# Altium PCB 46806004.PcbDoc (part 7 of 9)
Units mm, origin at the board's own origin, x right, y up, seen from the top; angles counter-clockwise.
Board outline 130 x 105 mm, 8 copper layers (Top Layer, P1-GND, L1-Signal, L2-Signal, L3-Signal, L4-Signal, P2-GND, Bottom Layer), stack 1.63 mm thick; 796 components, 496 nets, 2808 pads, 1195 vias.
Unrouted connection lines stored in the file: 1.
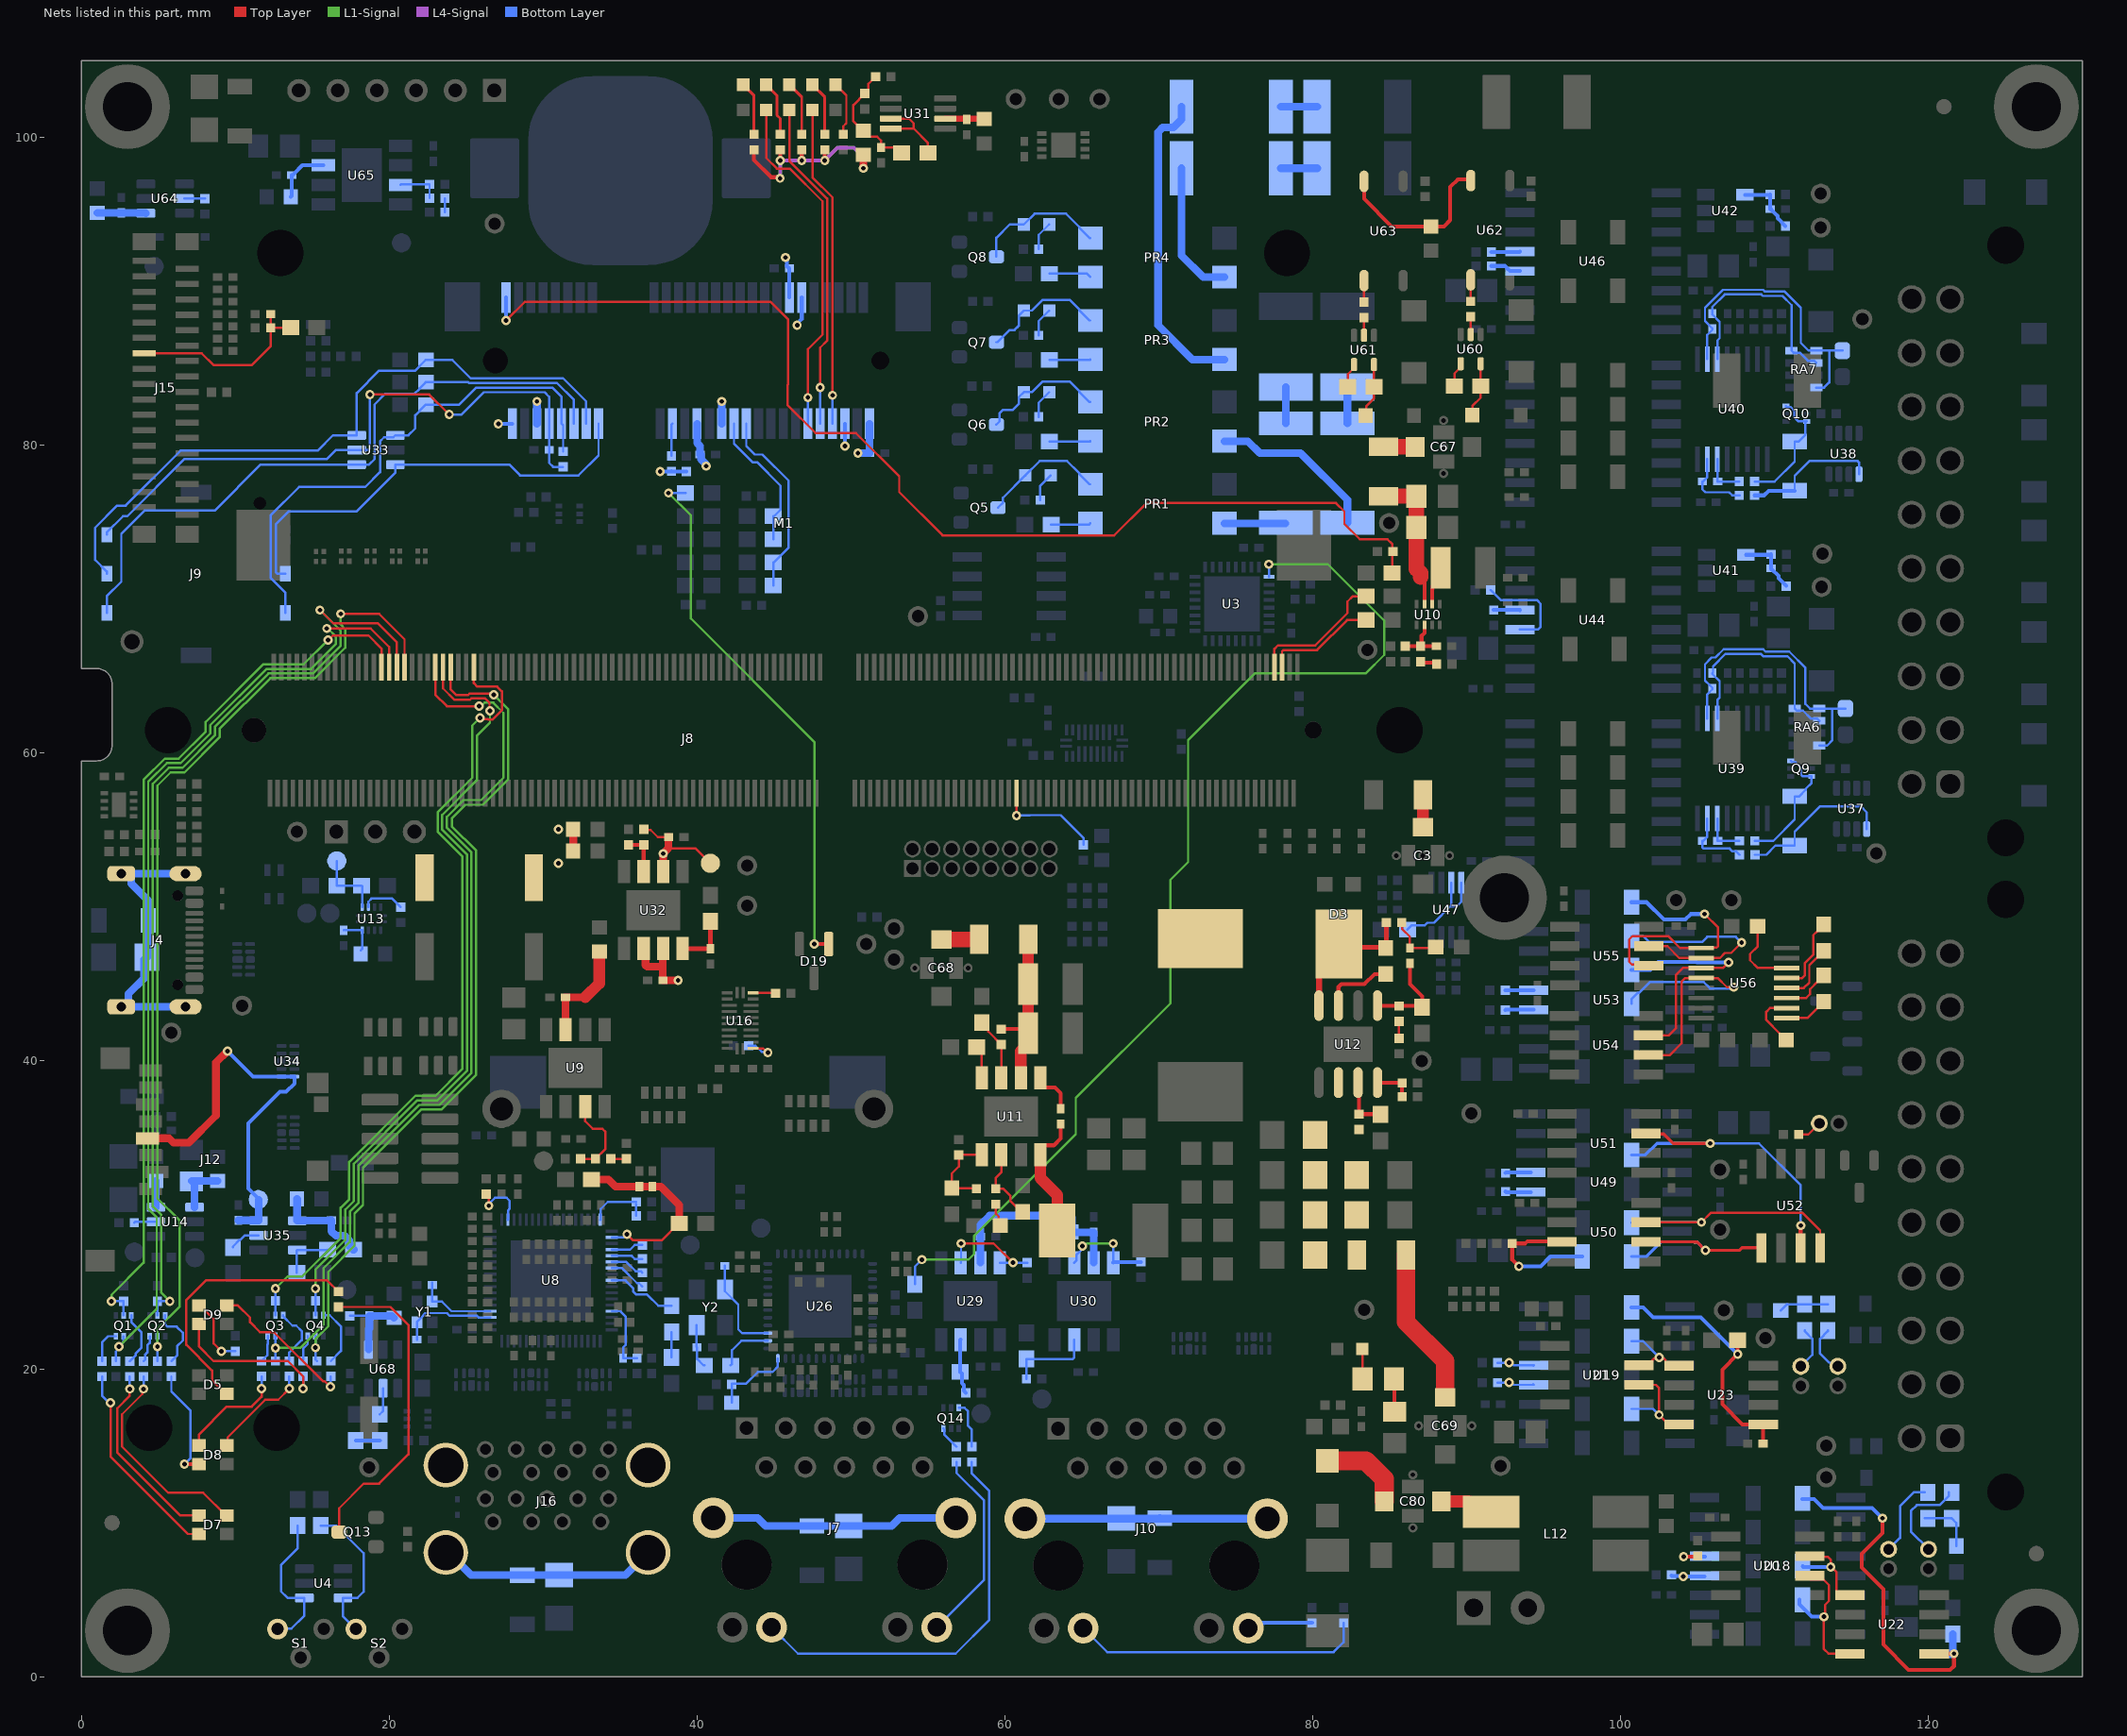
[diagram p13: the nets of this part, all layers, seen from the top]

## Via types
v1: diameter 0.6, hole 0.3, Top Layer to Bottom Layer, tented both sides, 1130 vias
v2: diameter 0.6, hole 0.3, Top Layer to Bottom Layer, 53 vias
v3: diameter 0.3, hole 0.3, Top Layer to Bottom Layer, 12 vias

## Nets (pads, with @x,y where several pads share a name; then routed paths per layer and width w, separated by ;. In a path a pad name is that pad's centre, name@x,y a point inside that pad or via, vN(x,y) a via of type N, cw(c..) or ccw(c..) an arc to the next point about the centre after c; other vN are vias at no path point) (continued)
LEDs.GPIO1: M1.30 Q1.2 R67.2 | length 57.7
  Top Layer w0.15: v1(16.025,67.35) 16.05,67.35 16.35,67.65 18.65,67.65 19.5,66.8 M1.30@19.5,65.6
  L1-Signal w0.15: v1(1.95,24.4) 1.971,24.421 1.971,24.821 4.05,26.9 4.05,58.265 5.435,59.65 6.327,59.65 8.084,61.407 8.084,62.034 11.828,65.778 14.453,65.778 v1(16.025,67.35)
  Bottom Layer w0.15: v1(1.95,24.4) R67.2@2.75,24.4 Q1.2@2.75,23.475
LEDs.GPIO2: M1.32 Q1.5 R70.2 | length 63.1
  Top Layer w0.15: v1(15.95,68.1) 18.8,68.1 20,66.9 M1.32@20,65.6
  L1-Signal w0.15: v1(2.45,21.45) 4.9,23.9 4.9,29.85 4.35,30.4 4.35,58.141 5.559,59.35 6.451,59.35 8.384,61.282 8.384,61.828 12.034,65.478 14.93,65.478 16.55,67.099 16.55,67.567 16.017,68.1 v1(15.95,68.1)
  Bottom Layer w0.15: R70.2@2.25,20.5 2.25,21.128 2.45,21.328 v1(2.45,21.45) 2.456,21.45 2.75,21.744 Q1.5@2.75,22.125
LEDs.GPIO3: M1.34 Q2.2 R71.2 | length 62.4
  Top Layer w0.15: v1(15.5,69.3) 16.35,68.45 19.25,68.45 20.5,67.2 M1.34@20.5,65.6
  L1-Signal w0.15: v1(5.75,24.4) 5.2,24.95 5.2,29.995 4.65,30.545 4.65,58.017 5.683,59.05 6.576,59.05 8.684,61.158 8.684,61.704 12.158,65.178 15.054,65.178 16.85,66.974 16.85,67.95 v1(15.5,69.3)
  Bottom Layer w0.15: Q2.2@4.95,23.475 R71.2@4.95,24.4 v1(5.75,24.4)
LEDs.GPIO4: M1.36 Q2.5 R74.2 | length 64.5
  Top Layer w0.15: v1(16.85,69.05) 19.35,69.05 21,67.4 M1.36@21,65.6
  L1-Signal w0.15: v1(4.95,21.45) 4.95,22.6 6.4,24.05 6.4,29.628 4.95,31.078 4.95,57.892 5.808,58.75 6.7,58.75 8.984,61.034 8.984,61.579 12.283,64.878 15.178,64.878 17.15,66.85 17.15,68.074 16.85,68.374 v1(16.85,69.05)
  Bottom Layer w0.15: R74.2@4.95,20.5 v1(4.95,21.45) Q2.5@4.95,22.125
LEDs.GPIO5: M1.54 Q3.2 R75.2 | length 53
  Top Layer w0.15: M1.54@25.5,65.6 25.5,64.55 25.725,64.325 27.017,64.325 27.325,64.017 27.325,62.783 26.733,62.191 26.429,62.191 26.412,62.208 25.986,62.208 v1(25.9,62.294)
  L1-Signal w0.15: v1(12.614,25.215) 13.399,26 14.35,26 16.85,28.5 16.85,30.475 17.4,31.025 17.4,33.447 21.703,37.75 23.015,37.75 24.75,39.485 24.75,53.3 23.15,54.9 23.15,56.15 25.4,58.4 25.4,61.794 v1(25.9,62.294)
  Bottom Layer w0.15: Q3.2@12.614,23.49 R75.2@12.614,24.415 v1(12.614,25.215)
LEDs.GPIO6: M1.44 Q3.5 R78.2 | length 59.6
  Top Layer w0.15: M1.44@23,65.6 23,63.8 23.75,63.05 v1(25.85,63.05)
  L1-Signal w0.15: v1(12.614,21.365) 14.215,21.365 15.75,22.9 15.75,26.551 17.45,28.251 17.45,30.226 18,30.776 18,33.199 21.951,37.15 23.263,37.15 25.35,39.237 25.35,53.549 23.75,55.149 23.75,55.867 24.839,56.956 25.982,56.956 27.425,58.399 27.425,62.617 26.767,63.275 26.197,63.275 25.972,63.05 v1(25.85,63.05)
  Bottom Layer w0.15: R78.2@12.614,20.515 v1(12.614,21.365) Q3.5@12.614,22.14
LEDs.GPIO7: M1.46 Q4.2 R79.2 | length 51.5
  Top Layer w0.15: M1.46@23.5,65.6 23.5,64.209 24.241,63.468 25.247,63.468 25.354,63.575 26.217,63.575 26.517,63.275 26.517,62.783 v1(26.55,62.75)
  L1-Signal w0.15: v1(15.214,25.215) 15.214,26.44 17.15,28.376 17.15,30.351 17.7,30.901 17.7,33.323 21.827,37.45 23.139,37.45 25.05,39.361 25.05,53.424 23.45,55.024 23.45,55.991 25.7,58.241 25.7,61.137 26.55,61.987 v1(26.55,62.75)
  Bottom Layer w0.15: Q4.2@15.214,23.49 R79.2@15.214,24.415 v1(15.214,25.215)
LEDs.GPIO8: M1.48 Q4.5 R81.2 | length 56.9
  Top Layer w0.15: M1.48@24,65.6 23.995,65.595 23.995,64.588 23.975,64.567 23.975,64.158 24.366,63.768 25.122,63.768 25.23,63.875 26.725,63.875 v1(26.8,63.8)
  L1-Signal w0.15: v1(15.214,21.377) 15.214,21.94 16.05,22.776 16.05,26.3 17.75,28 17.75,30.1 18.3,30.65 18.3,33.074 22.076,36.85 23.388,36.85 25.65,39.112 25.65,53.673 24.075,55.248 24.075,55.767 24.958,56.65 26.1,56.65 27.725,58.275 27.725,62.875 v1(26.8,63.8)
  Bottom Layer w0.15: Q4.5@15.214,22.14 v1(15.214,21.377) 15.214,20.615 R81.2@15.314,20.515
MPCI1_1V5: C180.2 J8.6 J8.28 J8.48 R149.2 U32.6 X55.1 | length 11.7
  Top Layer w0.15: R149.2@36.55,55.05 36.587,55.013 36.987,55.013 37.45,54.55 C180.2@38.15,54.55 ; 38.15,53.825 39.89,53.825 X55.1@40.865,52.85
  Top Layer w0.5: U32.6@37.8,52.3 v1(37.8,53.475) 38.15,53.825 C180.2@38.15,54.55
  Bottom Layer w0.25: v1(49.6,79.95) J8.48@49.6,81.4
  Bottom Layer w0.5: J8.6@29.6,81.4 v1(29.6,82.85) ; J8.28@41.6,81.4 v1(41.6,82.85)
MPCI1_3V3: C168.1 C169.1 C170.2 C171.2 C172.2 C174.2 J8.2 J8.24 J8.39 J8.41 J8.52 L27.2 L28.2 L30.2 R135.2 R141.1 R146.1 R151.2 R152.2 R153.2 U32.2 U32.3 | length 33.3
  Top Layer w0.25: R135.2@43.7,99.2 43.7,98.525 44.808,97.417 45.323,97.417 v1(45.39,97.35) ; v1(45.4,98.5) R151.2@45.4,99.2 ; v1(46.8,98.5) R152.2@46.8,99.2 ; v1(48.3,98.5) R153.2@48.3,99.2
  Top Layer w0.5: L28.2@31.96,53.654 L27.2@31.96,55.054 ; U32.2@36.53,47.3 36.649,47.181 36.649,46.237 36.753,46.133 37.769,46.133 ; C174.2@37.769,45.271 37.769,46.133 ; C174.2@37.79,45.25 v1(38.765,45.25) ; U32.3@37.8,47.3 37.769,47.269 37.769,46.133 ; v1(50.8,98) L30.2@50.8,98.86
  L4-Signal w0.25: v1(45.39,97.35) 45.395,97.355 45.395,98.495 v1(45.4,98.5) v1(46.8,98.5) v1(48.3,98.5) 49.12,99.32 50.18,99.32 50.8,98.7 v1(50.8,98)
  Bottom Layer w0.25: v1(27.09,81.4) J8.2@28,81.4 ; v1(37.6,78.3) 37.608,78.308 38.332,78.308 R141.1@38.34,78.316 ; R141.1@38.356,78.3 R146.1@39.3,78.3 ; v1(45.75,92.2) 45.75,92.105 45.825,92.03 45.825,91.625 45.95,91.5 C172.2@46,91.5 J8.39@46,89.6 ; v1(46.5,87.8) 46.5,87.895 46.8,88.195 J8.41@46.8,89.6
  Bottom Layer w0.5: J8.24@40,81.4 40,80.15 40.2,79.95 C171.2@40.2,79.4 40.25,79.4 40.25,79.095 40.581,78.764 40.581,78.669 v1(40.6,78.65) ; v1(50.45,79.5) C170.2@51.2,79.5 J8.52@51.2,81.4
  other v1: 31,52.85 31,55.05
NetC2_2: C2.2 J10.S R3.1 | length 15.8
  Bottom Layer w0.5: J10.S@61.3,10.269 70.019,10.269 R3.1@70.05,10.3 70.081,10.269 J10.S@77.05,10.269
NetC3_3: C3.3 L2.1 | length 2.1
  Top Layer w0.75: C3.3@87.15,55.2 L2.1@87.15,57.3
NetC22_2: C22.2 U8.55 Y1.1 | length 5.2
  Bottom Layer w0.15: C22.2@22.8,25.6 22.8,24.375 23.425,24.375 24.053,23.747 U8.55@26.564,23.747
NetC23_2: C23.2 U8.54 Y1.3 | length 6.3
  Bottom Layer w0.15: C23.2@21.8,21.9 Y1.3@21.8,23.025 21.8,23.05 22.225,23.475 22.225,23.493 22.357,23.625 23.751,23.625 23.928,23.447 25.703,23.447 25.803,23.347 U8.54@26.564,23.347
NetC28_2: C28.2 R14.1 U8.31 | length 4.7
  Bottom Layer w0.15: U8.31@34.459,23.747 35.003,23.747 35.373,23.377 35.373,21.573 35.2,21.4 C28.2@35.2,20.7 R14.1@36.1,20.7
NetC58_2: C58.2 L6.2 U9.3 | length 6.7
  Top Layer w0.5: C58.2@31.45,44.15 C58.2@31.458,44.15 ; U9.3@31.465,42.05 31.458,42.057 C58.2@31.458,44.15 ; 32.75,44.15 C58.2@31.458,44.15
  Top Layer w0.75: 32.75,44.15 33.65,45.05 L6.2@33.65,47.1
NetC64_2: C64.2 C65.2 R22.1 R23.2 U8.19 | length 12.7
  Top Layer w0.15: v1(35.45,28.75) 35.85,28.35 37.7,28.35 38.8,29.45 R22.1@38.85,29.45
  Top Layer w0.5: R23.2@33.15,32.3 34.25,32.3 34.7,31.85 C65.2@36.25,31.85 C64.2@37.1,31.85 37.65,31.85 38.85,30.65 R22.1@38.85,29.45
  Bottom Layer w0.15: U8.19@34.459,28.547 35.247,28.547 v1(35.45,28.75)
NetC67_3: C67.3 L8.1 | length 2.1
  Top Layer w1: L8.1@84.593,79.9 C67.3@86.65,79.9
NetC68_3: C68.3 L9.1 | length 2.5
  Top Layer w1: C68.3@55.875,47.9 L9.1@58.325,47.9
NetC69_3: C69.3 L10.1 | length 10.3
  Top Layer w1.2: L10.1@86.05,27.4 86.05,23.05 88.6,20.5 C69.3@88.6,18.15
NetC70_2: C70.2 C72.2 C75.2 C76.2 C78.2 C79.2 L10.2 R30.2 U12.2
NetC71_2: C71.2 C74.2 L8.2 U10.7 | length 9.4
  Top Layer w0.25: 86.998,71.45 87.104,71.45 87.25,71.304 U10.7@87.25,69.675
  Top Layer w1: L8.2@84.593,76.7 86.725,76.7 86.725,74.8 86.725,71.975 86.998,71.702 86.998,71.45
NetC73_2: C73.2 C77.2 L9.2 R28.2 U11.2 | length 11.1
  Top Layer w0.25: R28.2@59.765,42.075 61.225,42.075 C73.2@61.5,41.8
  Top Layer w0.75: U11.2@61.035,38.9 61.035,40.635 61.5,41.1 C73.2@61.5,41.8 61.513,41.813 61.513,47.887 L9.2@61.525,47.9
NetC80_1: C80.1 D2.2 | length 5.6
  Top Layer w1.25: D2.2@80.95,14.028 83.442,14.028 84.628,12.842 84.628,11.422 C80.1@84.65,11.4
NetC80_3: C80.3 L12.1 | length 3.5
  Top Layer w0.8: C80.3@88.35,11.4 90.12,11.4 90.8,10.72 L12.1@91.59,10.72
NetC81_1: C81.1 R35.1 | length 1.5
  Top Layer w0.15: R35.1@59.4,30.7 59.4,30.1 59.588,29.912 59.588,29.412 C81.1@59.7,29.3
NetC82_1: C82.1 U11.1 | length 2.9
  Top Layer w0.25: U11.1@62.305,38.9 62.305,38.549 62.581,38.273 63.253,38.273 63.625,37.901 C82.1@63.625,36.9
NetC82_2: C82.2 L13.1 U11.8 | length 8.2
  Top Layer w0.25: U11.8@62.305,33.9 62.305,34.252 62.581,34.528 63.178,34.528 63.625,34.975 C82.2@63.625,35.9
  Top Layer w0.75: U11.8@62.305,33.9 62.305,32.395 63.4,31.3 L13.1@63.4,29
NetC83_1: C83.1 R37.1 R38.2 U10.2 | length 3.4
  Top Layer w0.25: R38.2@86,66.95 R37.1@86.998,66.95 ; R37.1@86.998,66.946 87,66.948 88.02,66.948 C83.1@88.023,66.95 ; R37.1@87.062,67.012 87.062,67.625 87.25,67.813 U10.2@87.25,68.325
NetC84_1: C84.1 R35.2 U11.6 | length 4.8
  Top Layer w0.15: U11.6@59.765,33.9 59.765,32.765 59.4,32.4 R35.2@59.4,31.7 59.9,31.7 60.35,31.25 60.35,30.925 61.05,30.225 C84.1@61.05,30.2
NetC85_1: C85.1 D3.3 L14.1 R42.2 U12.8 | length 9.8
  Top Layer w0.3: D3.3@81.7,47.6 81.9,47.4 84.775,47.4 R42.2@84.775,49
  Top Layer w0.4: U12.8@80.395,43.6 80.395,46.295 D3.3@81.7,47.6
  Top Layer w0.75: D3.3@81.343,47.957 D3.3@81.7,47.6
NetC85_2: C85.2 U12.7 | length 4.6
  Top Layer w0.25: U12.7@81.665,43.6 81.665,44.815 81.85,45 83.35,45 84,45.65 C85.2@84.725,45.65
NetC87_2: C87.2 R39.1 R40.2 U11.5 | length 5.5
  Top Layer w0.15: R39.1@58.15,31.7 58.1,31.75 C87.2@56.55,31.75 56.55,32.7 57,33.15 R40.2@57,33.9 U11.5@58.495,33.9
NetC90_1: C90.1 R44.1 R45.2 U12.5 | length 6.1
  Top Layer w0.25: U12.5@84.205,43.6 87,43.6 R44.1@87.1,43.5 87.1,43.6 87.1,44.2 86.3,45 C90.1@86.3,46.35
NetC90_2: C90.2 C93.1 R42.1 | length 3.6
  Top Layer w0.15: R42.1@85.775,49 85.817,48.958 85.817,48.563 86.3,48.08 C90.2@86.3,47.35 87.925,47.35 C93.1@87.975,47.4
NetC104_2: C104.2 L15.2 U14.1 | length 3.4
  Bottom Layer w0.5: U14.1@7.36,30.5 7.36,32.035 7.185,32.21 L15.2@8.85,32.21
NetC106_2: C106.2 L16.2 U13.12 | length 2.5
  Bottom Layer w0.15: C106.2@17.05,48.5 U13.12@18.25,48.5 18.25,47.29 L16.2@18.16,47.2
NetC109_2: C109.2 J4.SH1 J4.SH2 J4.SH3 J4.SH4 R66.1 | length 18.6
  Bottom Layer w0.5: J4.SH4@2.595,43.53 J4.SH4@2.82,43.53 ; J4.SH2@6.775,43.53 J4.SH4@2.82,43.53 ; J4.SH1@6.775,52.17 J4.SH3@2.595,52.17 2.995,52.17 3.245,51.92 3.245,51.52 4.35,50.415 R66.1@4.35,49.15 4.35,46.85 4.093,46.593 4.093,45.393 3.07,44.37 3.07,43.78 J4.SH4@2.82,43.53
NetC127_2: C127.2 R91.1 R92.1 U22.5 | length 25
  Top Layer w0.25: v1(117,10.3) 117,9.343 115.65,7.993 115.65,7.1 117.053,5.697 117.053,2.097 118.7,0.45 121.4,0.45 121.65,0.7 v1(121.65,1.5) 121.648,1.502 U22.5@120.163,1.502
  Bottom Layer w0.25: R91.1@111.8,11.55 112.55,11.55 113.14,10.96 116.34,10.96 v1(117,10.3)
  Bottom Layer w0.5: C127.2@120.7,1.45 121.584,1.45 121.634,1.5 v1(121.65,1.5) 121.65,1.595 121.567,1.678 R92.1@121.567,2.776
NetC128_2: C128.2 R90.2 R93.1 U23.5 | length 17.2
  Top Layer w0.25: R93.1@107.6,21.862 v1(107.6,20.95) 106.6,19.95 106.6,17.696 107.906,16.39 U23.5@109.261,16.39 109.25,16.379 C128.2@109.25,15.15
  Bottom Layer w0.25: R90.2@100.7,24 101.45,24 102.1,23.35 105.2,23.35 v1(107.6,20.95)
NetC131_2: C131.2 R95.1 R97.1 | length 3.2
  Bottom Layer w0.15: C131.2@110.4,23.8 110.8,24.2 R95.1@113.45,24.2
NetC132_2: C132.2 R94.1 R96.1 | length 3.7
  Bottom Layer w0.15: R94.1@119.75,10.3 R96.1@121.5,10.3 ; R96.1@121.5,10.285 121.8,9.985 C132.2@121.8,8.5
NetC139_2: C139.2 R119.2 Y2.1 | length 2.8
  Bottom Layer w0.15: C139.2@39.975,21.425 Y2.1@39.975,22.85 ; C139.2@40,21.4 40,20.7 40,20.65 40.425,20.225 R119.2@40.475,20.225
NetC142_2: C142.2 U26.15 Y2.3 | length 6.5
  Bottom Layer w0.15: C142.2@41.8,26.7 41.8,25.05 42.678,24.172 42.678,22.572 42.925,22.325 U26.15@44.6,22.325
NetC156_2: C156.2 R122.1 U26.12 | length 5.2
  Bottom Layer w0.15: C156.2@42.25,17.8 R122.1@42.25,19 42.25,19.05 43.2,19.05 43.953,19.803 44.903,19.803 45.25,20.15 U26.12@45.25,20.675
NetC158_2: C158.2 C159.2 L26.2 U29.3 U30.3 | length 12.9
  Bottom Layer w0.5: U29.3@58.4,26.9 58.4,29.35 59.008,29.958 64.194,29.958 64.34,29.812 L26.2@64.34,28.91 ; L26.2@64.44,28.9 64.46,28.88 C159.2@65.77,28.88 U30.3@65.77,26.9
NetC163_2: C163.2 J7.S R131.1 | length 16.2
  Bottom Layer w0.5: J7.S@41.06,10.319 43.931,10.319 44.45,9.8 R131.1@47.45,9.8 C163.2@49.85,9.8 52.65,9.8 53.169,10.319 J7.S@56.81,10.319
NetC167_2: C167.2 L29.2 U31.2 | length 2.5
  Top Layer w0.25: L29.2@58.615,101.225 L29.2@58.65,101.19
  Top Layer w0.4: U31.2@56.12,101.225 L29.2@58.615,101.225
NetC173_2: C173.2 L30.1 R134.1 R136.2 R137.2 | length 7.8
  Top Layer w0.15: R137.2@51.6,103.95 51.125,103.475 51.125,103.075 R136.2@50.9,102.85 50.15,102.1 50.15,101.06 50.77,100.44 L30.1@50.8,100.44 51.185,100.055 51.695,100.055 51.95,99.8 C173.2@51.95,99.35 52.95,99.35 R134.1@53.3,99
NetC175_2: C175.2 J8.8 J9.C1 R139.2 U33.5 | length 41.2
  Top Layer w0.15: v1(18.75,83.3) 22.6,83.3 v1(23.9,82)
  Bottom Layer w0.15: J9.C1@1.655,74.19 1.655,74.34 2.715,75.4 3,75.4 6.716,79.116 15.966,79.116 16.55,79.7 18.637,79.7 18.75,79.813 v1(18.75,83.3) ; v1(23.9,82) 24.7,82 26.15,83.45 30.1,83.45 30.4,83.15 J8.8@30.4,81.4 C175.2@30.4,79.7 30.4,78.85 30.65,78.6 R139.2@31.3,78.6
NetC176_2: C176.2 R138.1 U32.4 | length 3.6
  Top Layer w0.3: U32.4@39.07,47.3 C176.2@40.865,47.3 R138.1@40.865,49.07
NetC177_2: C177.2 J8.10 J9.C7 R139.1 U33.1 | length 34.6
  Bottom Layer w0.15: J9.C7@13.245,69.11 13.245,70.445 12.3,71.39 12.3,75.45 14.15,77.3 18.45,77.3 19.41,78.26 19.41,80.26 19.667,80.517 20.272,80.517 U33.1@20.405,80.65 21.25,80.65 21.7,81.1 21.7,81.95 21.975,82.225 21.975,82.25 22.375,82.65 C177.2@22.4,82.65 24.55,82.65 25.65,83.75 30.6,83.75 31.2,83.15 J8.10@31.2,81.4 31.3,81.3 R139.1@31.3,79.6
NetC178_2: C178.2 J8.12 J9.C3 U33.4 | length 43.1
  Bottom Layer w0.15: J9.C3@1.655,69.11 1.655,70.195 2.6,71.14 2.6,74.25 4.111,75.761 8.661,75.761 11.65,78.75 U33.4@17.895,78.75 18.7,78.75 19.05,79.1 19.05,82.648 19.752,83.35 21.65,83.35 21.975,83.675 21.975,83.7 22.375,84.1 C178.2@22.4,84.1 25.126,84.1 25.176,84.05 30.9,84.05 32,82.95 J8.12@32,81.4
NetC179_2: C179.2 J8.14 J9.C2 U33.6 | length 43.9
  Bottom Layer w0.15: J9.C2@1.655,71.65 1.655,71.8 0.9,72.555 0.9,74.65 2.334,76.084 2.884,76.084 6.45,79.65 15.35,79.65 16.35,80.65 U33.6@17.895,80.65 17.895,83.395 19.35,84.85 21.7,84.85 21.975,85.125 21.975,85.15 22.375,85.55 C179.2@22.4,85.55 24.1,85.55 25.3,84.35 31.3,84.35 32.8,82.85 J8.14@32.8,81.4
NetC181_2: C181.2 L31.2 R154.2 U35.1 | length 6.5
  Bottom Layer w0.5: L31.2@14.01,31.05 14.026,31.034 U35.1@14.026,29.631 16.181,29.631 C181.2@16.2,29.65 ; C181.2@16.25,29.65 16.25,28.943 16.543,28.65 17.107,28.65 17.4,28.357 17.4,28 17.65,27.75 R154.2@17.7,27.75
NetC182_2: C182.2 J12.4 U34.5 U34.6 U35.6 X57.1 | length 27.3
  Top Layer w0.5: J12.4@4.303,34.985 5.703,34.985 5.988,34.7 6.99,34.7 8.75,36.46 8.75,39.9 v1(9.5,40.65)
  Bottom Layer w0.25: v1(9.5,40.65) 11.162,38.987 U34.6@13.008,38.987 U34.5@13.842,38.987 13.842,38.542 13.3,38 12.9,38 10.85,35.95 10.85,31.728 11.5,31.078 X57.1@11.5,31 X57.1@11.516,30.984 ; U35.6@11.497,29.65 U35.6@11.516,29.631
  Bottom Layer w0.5: C182.2@10.2,29.65 U35.6@11.497,29.65 ; U35.6@11.516,29.631 X57.1@11.516,30.984
NetC185_1: C185.1 R161.2 U39.7 | length 4.6
  Bottom Layer w0.15: U39.7@105.625,55.75 105.625,54.575 105.35,54.3 C185.1@105.3,54.3 105.3,53.888 105.388,53.8 107.077,53.8 107.252,53.625 107.492,53.625 R161.2@107.717,53.4
NetC185_2: C185.2 R160.2 U39.6 | length 2.9
  Bottom Layer w0.15: U39.6@106.275,55.75 106.275,54.325 C185.2@106.3,54.3 R160.2@107.71,54.3
NetC186_1: C186.1 JP1.2 RA6.5 RA6.8 U39.10 | length 19.4
  Bottom Layer w0.15: U39.10@105.625,62.25 105.625,63.825 105.95,64.15 105.95,64.25 105.775,64.425 105.475,64.725 105.475,65.775 105.915,66.215 106.15,66.215 106.688,66.753 109.254,66.753 109.407,66.6 110.95,66.6 112,65.55 112,63.2 112.3,62.9 RA6.5@112.9,62.9 113.75,62.9 ; RA6.8@112.9,60.5 113.409,60.5 113.75,60.841 113.75,62.9 ; JP1.2@114.6,62.9 113.75,62.9
NetC186_2: C186.2 RA6.4 RA6.6 U39.11 | length 14.4
  Bottom Layer w0.15: U39.11@106.275,62.25 106.275,63.457 106.425,63.607 106.425,64.675 105.95,65.15 C186.2@105.95,65.2 105.996,65.246 105.996,65.637 106.812,66.453 109.097,66.453 109.25,66.3 110.826,66.3 111.3,65.826 RA6.4@111.3,62.9 111.434,62.766 111.834,62.766 112.35,62.25 112.75,62.25 RA6.6@112.9,62.1
NetC187_1: C187.1 R163.2 U40.7 | length 4.7
  Bottom Layer w0.15: U40.7@105.625,79.1 105.625,77.925 105.35,77.65 C187.1@105.3,77.65 105.3,77.15 105.5,76.95 107.05,76.95 107.25,76.75 R163.2@107.717,76.75
NetC187_2: C187.2 R162.2 U40.6 | length 2.9
  Bottom Layer w0.15: U40.6@106.275,79.1 106.275,77.675 C187.2@106.3,77.65 R162.2@107.71,77.65
NetC188_1: C188.1 JP2.2 RA7.5 RA7.8 U40.10 | length 19.1
  Bottom Layer w0.15: U40.10@105.625,85.6 105.625,87.175 105.95,87.5 C188.1@105.95,87.55 105.95,87.6 105.475,88.075 105.475,88.943 106.635,90.103 109.257,90.103 109.357,90.003 110.627,90.003 111.7,88.93 111.7,86.654 112.204,86.15 RA7.5@112.7,86.15 113.55,86.15 ; RA7.8@112.7,83.75 113.209,83.75 113.55,84.091 113.55,86.15 ; JP2.2@114.4,86.15 113.55,86.15
NetC188_2: C188.2 RA7.4 RA7.6 U40.11 | length 14.3
  Bottom Layer w0.15: U40.11@106.275,85.6 106.275,86.807 106.425,86.957 106.425,88.025 105.95,88.5 105.95,88.994 106.759,89.803 109.132,89.803 109.233,89.703 110.503,89.703 111.1,89.106 RA7.4@111.1,86.15 111.234,86.016 111.634,86.016 112.15,85.5 112.55,85.5 RA7.6@112.7,85.35
NetC189_2: C189.2 R164.2 R166.2 U42.4 | length 4.1
  Bottom Layer w0.25: U42.4@108.07,96.269 109.669,96.269 R166.2@109.7,96.3 C189.2@109.7,95.35 109.75,95.35 110.2,94.9 110.2,94.75 R164.2@110.7,94.25
NetC190_2: C190.2 R165.2 R167.2 U41.4 | length 4.1
  Bottom Layer w0.25: U41.4@108.13,72.884 109.729,72.884 R167.2@109.76,72.915 109.76,71.965 109.81,71.965 110.26,71.515 110.26,71.365 R165.2@110.76,70.865
NetC234_1: C234.1 U56.3 | length 3.2
  Top Layer w0.15: U56.3@110.775,44.093 112.043,44.093 112.3,44.35 112.3,44.668 112.775,45.143 112.8,45.143 113.2,45.543 C234.1@113.2,45.568
NetC234_2: C234.2 U56.1 | length 2.9
  Top Layer w0.15: U56.1@110.775,42.793 112.125,42.793 112.775,43.443 112.8,43.443 113.2,43.843 C234.2@113.2,43.868
NetC235_1: C235.1 U56.5 | length 5.1
  Top Layer w0.15: U56.5@110.775,45.393 111.793,45.393 111.95,45.55 111.95,46.35 112.5,46.9 112.5,48.168 112.775,48.443 112.8,48.443 113.2,48.843 C235.1@113.2,48.868
NetC235_2: C235.2 U56.4 | length 4.1
  Top Layer w0.15: U56.4@110.775,44.743 111.893,44.743 112.25,45.1 112.25,46.218 112.775,46.743 112.8,46.743 113.2,47.143 C235.2@113.2,47.168
NetC236_2: C236.2 U56.6 | length 5
  Top Layer w0.15: C236.2@108.9,48.768 108.9,47.45 108.4,46.95 108.4,46.55 108.907,46.043 U56.6@110.775,46.043
NetC238_2: C238.2 U56.2 | length 3.8
  Top Layer w0.15: C238.2@110.75,41.368 110.725,41.368 110.325,41.768 110.325,41.793 109.45,42.668 109.45,43.2 109.693,43.443 U56.2@110.775,43.443
NetC239_2: C239.2 L33.2 U65.3 | length 3.7
  Bottom Layer w0.25: L33.2@13.615,96.15 13.675,96.21 C239.2@13.675,97.547 13.725,97.547 13.85,97.672 13.85,97.675 14.36,98.185 U65.3@15.725,98.185
NetC241_2: C241.2 L34.2 U64.1 | length 3.2
  Bottom Layer w0.5: L34.2@1.05,95.1 4.173,95.1 U64.1@4.195,95.078
NetC245_2: C245.2 J15.22 R209.2 R210.1 | length 12.5
  Top Layer w0.15: J15.22@4.081,85.978 7.822,85.978 8.6,85.2 11.076,85.2 12.3,86.424 R210.1@12.3,87.628 ; C245.2@12.3,88.528 R210.1@12.3,87.628 ; R209.2@13.6,87.65 13.578,87.628 R210.1@12.3,87.628
NetC253_2: C253.2 L40.2 R223.2 U68.1 | length 5.1
  Bottom Layer w0.15: R223.2@17.45,23.45 C253.2@18.711,23.45
  Bottom Layer w0.5: U68.1@18.661,21.255 18.661,22.577 18.711,22.627 C253.2@18.711,23.45 20.171,23.45 L40.2@20.311,23.31
NetC257_2: C257.2 J16.S1 J16.S2 J16.S3 J16.S4 R214.1 | length 14.4
  Bottom Layer w0.5: J16.S1@23.68,8.069 23.853,8.069 25.322,6.6 R214.1@28.65,6.6 C257.2@31.05,6.6 34.45,6.6 35.351,6.6 J16.S4@36.82,8.069
NetD4_1: D4.1 R43.2 | length 2
  Top Layer w0.15: R43.2@83.225,19.35 D4.1@83.225,21.3
NetD5_3: D5.3 R47.2 | length 17.9
  Top Layer w0.15: D5.3@9.45,18.375 9.4,18.375 8.5,19.275 8.5,19.893 6.825,21.568 6.825,24.475 8.1,25.75 15.975,25.75 R47.2@16.7,25.025
NetD6_1: D6.1 R50.1 | length 3.6
  Top Layer w0.15: D6.1@49,103.425 49.7,102.725 49.7,100.924 49.502,100.725 R50.1@49.502,100.2
NetD7_2: D7.2 R72.2 | length 13.8
  Top Layer w0.15: v1(4.05,18.7) 3.964,18.614 3.964,18.364 2.65,17.05 2.65,14.95 5.65,11.95 7.925,11.95 9.4,10.475 D7.2@9.45,10.475
  Bottom Layer w0.15: v1(4.05,18.7) R72.2@4.05,19.5
NetD7_3: D7.3 R69.2 | length 12.3
  Top Layer w0.15: v1(3.15,18.7) 3.15,18.25 2.35,17.45 2.35,14.55 6.425,10.475 D7.3@7.65,10.475
  Bottom Layer w0.15: v1(3.15,18.7) R69.2@3.15,19.5
NetD7_4: D7.4 R68.2 | length 13.3
  Top Layer w0.15: v1(1.9,17.8) 1.9,14.3 6.925,9.275 D7.4@7.65,9.275
  Bottom Layer w0.15: R68.2@1.35,19.5 1.35,18.25 1.8,17.8 v1(1.9,17.8)
NetD8_2: D8.2 R77.2 | length 6.7
  Top Layer w0.15: D8.2@9.45,15.025 9.512,15.087 9.512,15.562 11.95,18 12.799,18 v1(13.514,18.715)
  Bottom Layer w0.15: v1(13.514,18.715) R77.2@13.514,19.515
NetD8_3: D8.3 R76.2 | length 7.1
  Top Layer w0.15: D8.3@7.65,15.025 7.65,15.744 9.45,17.544 11.07,17.544 11.714,18.189 v1(11.714,18.715)
  Bottom Layer w0.15: v1(11.714,18.715) R76.2@11.714,19.515
NetD8_4: D8.4 R73.2 | length 7.3
  Top Layer w0.25: v1(6.7,13.812) 7.637,13.812 D8.4@7.65,13.825
  Bottom Layer w0.15: R73.2@5.85,19.5 5.85,18.528 7.1,17.278 7.1,14.212 v1(6.7,13.812)
NetD9_2: D9.2 R83.2 | length 9.8
  Top Layer w0.15: D9.2@9.45,24.125 10.175,24.125 10.964,23.336 10.964,23.036 11.614,22.386 12.514,22.386 15.697,19.203 15.803,19.203 16.156,18.85 v1(16.192,18.85)
  Bottom Layer w0.15: v1(16.192,18.85) 16.192,19.493 R83.2@16.214,19.515
NetD9_3: D9.3 R82.2 | length 4.5
  Top Layer w0.15: D9.3@7.65,24.125 7.7,24.125 8.6,23.225 8.6,21.65 v1(9.1,21.15)
  Bottom Layer w0.15: v1(9.1,21.15) R82.2@10,21.15
NetD9_4: D9.4 R80.2 | length 10.6
  Top Layer w0.15: D9.4@7.65,22.925 7.65,21.45 8.585,20.515 13.414,20.515 14.414,19.515 v1(14.414,18.715)
  Bottom Layer w0.15: v1(14.414,18.715) R80.2@14.414,19.515
NetD10_1: D10.1 R100.2 | length 1.9
  Bottom Layer w0.15: R100.2@62.197,87.149 62.197,88.074 D10.1@62.872,88.749
NetD10_2: D10.2 PR3.2 Q7.3 | length 8.2
  Bottom Layer w0.15: Q7.3@59.447,86.699 59.522,86.699 60.314,87.49 60.621,87.49 60.804,87.674 60.81,87.674 60.897,87.761 60.897,88.424 61.228,88.754 61.76,88.754 62.454,89.449 64.211,89.449 64.825,88.835 64.825,88.785 65.5,88.11 PR3.2@65.55,88.11
NetD11_1: D11.1 R101.2 | length 1.9
  Bottom Layer w0.15: R101.2@62.197,92.749 62.197,93.674 D11.1@62.872,94.349
NetD11_2: D11.2 PR4.2 Q8.3 | length 8.7
  Bottom Layer w0.15: Q8.3@59.447,92.249 59.447,93.48 60.316,94.349 D11.2@61.222,94.349 61.922,95.049 63.971,95.049 64.825,94.195 64.825,94.145 65.5,93.47 PR4.2@65.55,93.47
NetD12_1: D12.1 R98.2 | length 1.9
  Bottom Layer w0.15: R98.2@62.297,76.449 62.297,77.374 D12.1@62.972,78.049
NetD12_2: D12.2 PR1.2 Q5.3 | length 8.1
  Bottom Layer w0.15: Q5.3@59.547,75.949 59.872,76.274 59.872,76.599 D12.2@61.322,78.049 62.264,78.99 64.03,78.99 64.825,78.195 64.825,78.145 65.5,77.47 PR1.2@65.55,77.47
NetD13_1: D13.1 R99.2 | length 1.9
  Bottom Layer w0.15: R99.2@62.197,81.849 62.197,82.774 D13.1@62.872,83.449
NetD13_2: D13.2 PR2.2 Q6.3 | length 8.4
  Bottom Layer w0.15: Q6.3@59.447,81.349 59.66,81.561 59.66,82.1 59.85,82.29 60.5,82.29 60.897,82.688 60.897,83.124 61.228,83.454 61.76,83.454 62.454,84.149 64.211,84.149 64.825,83.535 64.825,83.485 65.5,82.81 PR2.2@65.55,82.81
NetD18_1: D18.1 R135.1 | length 3.5
  Top Layer w0.18: D18.1@43,103.425 43.7,102.725 R135.1@43.7,100.2
NetD19_1: D19.1 R148.1 | length 35.3
  Top Layer w0.25: v1(47.62,47.6) D19.1@48.55,47.6
  L1-Signal w0.15: v1(38.15,76.9) 39.6,75.45 39.6,68.75 47.625,60.725 47.625,49.765 47.62,49.76 v1(47.62,47.6)
  Bottom Layer w0.15: v1(38.15,76.9) R148.1@39.25,76.9
NetD20_1: D20.1 R151.1 | length 3.6
  Top Layer w0.18: D20.1@44.5,103.425 45.2,102.725 45.2,101.436 45.4,101.236 R151.1@45.4,100.2
NetD20_2: D20.2 J8.42 | length 22.8
  Top Layer w0.15: D20.2@44.5,101.775 44.5,98.658 45.183,97.975 46.025,97.975 48.15,95.85 48.15,87.2 47.2,86.25 v1(47.2,83.1)
  Bottom Layer w0.15: J8.42@47.2,81.4 v1(47.2,83.1)
NetD21_1: D21.1 R152.1 | length 3.6
  Top Layer w0.18: D21.1@46,103.425 46.8,102.625 R152.1@46.8,100.2
NetD21_2: D21.2 J8.44 | length 21.6
  Top Layer w0.15: D21.2@46,101.775 46,98.475 48.45,96.025 48.45,86.8 48,86.35 v1(48,83.75)
  Bottom Layer w0.15: J8.44@48,81.4 v1(48,83.75)
NetD22_1: D22.1 R153.1 | length 3.6
  Top Layer w0.18: D22.1@47.5,103.425 48.3,102.625 R153.1@48.3,100.2
NetD22_2: D22.2 J8.46 | length 20.9
  Top Layer w0.15: D22.2@47.5,101.775 47.5,97.4 48.8,96.1 v1(48.8,83.25)
  Bottom Layer w0.15: J8.46@48.8,81.4 v1(48.8,83.25)
NetD29_3: D29.3 R195.2 U60.5 | length 3.6
  Top Layer w0.15: D29.3@90.355,81.948 90.367,81.961 90.367,82.561 90.905,83.098 R195.2@90.905,83.848 U60.5@90.905,85.298
NetD30_3: D30.3 R196.2 U61.5 | length 3.6
  Top Layer w0.15: D30.3@83.425,81.925 83.462,81.962 83.462,82.537 83.975,83.05 R196.2@83.975,83.8 U61.5@83.975,85.25
NetJ7_12: J7.12 R123.2 | length 26.5
  Bottom Layer w0.15: J7.12@44.845,3.209 46.554,1.5 56.8,1.5 58.986,3.686 58.986,12.064 57.85,13.2 R123.2@57.85,13.95
NetJ7_14: J7.14 R124.2 | length 12.8
  Bottom Layer w0.15: J7.14@55.565,3.209 58.65,6.294 58.65,11.45 56.85,13.25 R124.2@56.85,13.95
NetJ8_1: J8.1 R132.2 R133.2 | length 74.1
  Top Layer w0.15: v1(27.6,88.109) 28.805,89.314 44.786,89.314 45.9,88.2 45.9,83.95 45.875,83.925 45.875,82.625 47.7,80.8 50.317,80.8 53.134,77.984 53.134,76.966 55.95,74.15 67.1,74.15 69.2,76.25 81.506,76.25 82.05,75.706 82.05,74.9 83.05,73.9 84.85,73.9 85.15,73.6 R132.2@85.15,71.7
  Bottom Layer w0.25: v1(27.6,88.109) J8.1@27.6,89.6
NetJ8_16: J8.16 J9.C6 U33.3 | length 29.5
  Bottom Layer w0.15: J9.C6@13.245,71.65 12.738,71.65 12.65,71.738 12.65,74.891 13.459,75.7 17.87,75.7 20.405,78.235 U33.3@20.405,78.75 27.8,78.75 28.5,78.05 32.3,78.05 33.6,79.35 J8.16@33.6,81.4
NetJ8_20: J8.20 R141.2 | length 2.1
  Bottom Layer w0.15: R141.2@38.34,79.316 38.34,81.34 J8.20@38.4,81.4
NetJ8_30: J8.30 R142.2 R145.2 | length 9.2
  Bottom Layer w0.15: J8.30@42.4,81.4 42.4,80.1 43.6,78.9 43.9,78.9 45.425,77.375 45.425,75.825 45,75.4 R145.2@44.95,75.4 R142.2@44.95,73.9
NetJ8_32: J8.32 R143.2 R144.2 | length 12.4
  Bottom Layer w0.15: J8.32@43.2,81.4 43.2,79.95 43.75,79.4 44.25,79.4 45.95,77.7 45.95,73.35 45,72.4 R143.2@44.95,72.4 R144.2@44.95,70.9
NetJ10_12: J10.12 R1.1 | length 19.1
  Bottom Layer w0.15: J10.12@65.085,3.159 66.644,1.6 81.35,1.6 82,2.25 R1.1@82,3.5
NetJ10_14: J10.14 R2.1 | length 4.3
  Bottom Layer w0.25: J10.14@75.805,3.159 76.14,3.494 76.82,3.494 76.826,3.5 R2.1@79.95,3.5
NetJ14_1: J14.1 R190.2 | length 1.6
  Top Layer w0.15: R190.2@111.563,35.228 112.178,35.228 J14.1@112.9,35.95
NetJ18_1: J18.1 R94.2 | length 5.1
  Bottom Layer w0.15: J18.1@117.4,8.285 118.141,9.026 118.141,11.091 119.05,12 R94.2@119.75,12
NetJ19_1: J19.1 R96.2 | length 6.1
  Bottom Layer w0.15: J19.1@120,8.285 118.85,9.435 118.85,10.768 119.232,11.15 120.715,11.15 121.3,11.735 R96.2@121.3,12
NetJ20_1: J20.1 R95.2 | length 3.2
  Bottom Layer w0.15: R95.2@113.45,22.5 113.45,22.45 112.95,21.95 112.95,21 113.542,20.408 113.605,20.408 113.843,20.17 J20.1@114.1,20.17
NetJ21_1: J21.1 R97.2 | length 2.8
  Bottom Layer w0.15: J21.1@111.7,20.17 112.45,20.92 112.45,21.95 111.95,22.45 R97.2@111.95,22.5
NetL11_1: L11.1 U10.6 | length 2.6
  Top Layer w0.25: U10.6@87.748,69.675 87.748,69.894 87.75,69.896 87.75,70.674 87.773,70.697 87.773,70.821 88.3,71.347 L11.1@88.3,72.046
NetL17_1: L17.1 U14.6 | length 1.7
  Bottom Layer w0.5: U14.6@4.85,30.5 L17.1@4.85,32.21
NetL32_1: L32.1 U62.4 U63.4 | length 11.4
  Top Layer w0.25: U63.4@83.325,97.15 83.325,96.023 85.125,94.223 L32.1@87.705,94.223 ; L32.1@87.675,94.223 88.522,94.223 88.925,94.626 88.925,96.783 89.425,97.283 90.17,97.283 U62.4@90.255,97.198
NetM1_187: M1.187 R4.2 | length 6.9
  Top Layer w0.15: v1(60.75,55.95) M1.187@60.75,57.4
  Bottom Layer w0.15: v1(60.75,55.95) 61.6,55.95 61.625,55.975 63.625,55.975 65.1,54.5 R4.2@65.1,54.05
NetM1_254: M1.254 R5.2 | length 9
  Top Layer w0.15: M1.254@77.5,65.6 77.5,66.776 77.724,67 80.15,67 82.25,69.1 82.25,69.85 82.6,70.2 R5.2@83.45,70.2
NetM1_256: M1.256 R6.2 | length 7.3
  Top Layer w0.15: M1.256@78,65.6 78,66.612 78.088,66.7 80.274,66.7 82.224,68.65 R6.2@83.45,68.65
NetPR1_1: PR1.1 R102.2 | length 2.6
  Bottom Layer w0.15: R102.2@62.997,74.849 65.468,74.849 PR1.1@65.55,74.93
NetPR1_4: PR1.4 R110.2 | length 4
  Bottom Layer w0.15: R110.2@78.205,74.93 R110.2@78.25,74.975
  Bottom Layer w0.5: PR1.4@74.25,74.93 R110.2@78.205,74.93
NetPR2_1: PR2.1 R103.2 | length 2.7
  Bottom Layer w0.15: R103.2@62.897,80.249 65.528,80.249 PR2.1@65.55,80.27
NetPR2_4: PR2.4 R111.2 | length 11.1
  Bottom Layer w0.5: PR2.4@74.25,80.27 75.78,80.27 76.55,79.5 79.2,79.5 82.25,76.45 R111.2@82.25,74.975
NetPR3_1: PR3.1 R104.2 | length 2.7
  Bottom Layer w0.15: R104.2@62.897,85.549 65.528,85.549 PR3.1@65.55,85.57
NetPR3_4: PR3.4 R112.2 | length 20.5
  Bottom Layer w0.5: R112.2@71.475,102 71.475,101.171 70.95,100.646 70.243,100.646 69.95,100.354 69.95,87.8 72.18,85.57 PR3.4@74.25,85.57
NetPR4_1: PR4.1 R105.2 | length 2.7
  Bottom Layer w0.15: R105.2@62.897,91.149 65.331,91.149 PR4.1@65.55,90.93
NetPR4_4: PR4.4 R113.2 | length 9
  Bottom Layer w0.5: R113.2@71.475,98 71.475,92.325 72.87,90.93 PR4.4@74.25,90.93
NetPTC1_1: PTC1.1 R110.1 | length 2.4
  Bottom Layer w0.5: R110.1@78.25,81.425 PTC1.1@78.25,83.784
NetPTC2_1: PTC2.1 R111.1 | length 2.4
  Bottom Layer w0.5: R111.1@82.25,81.425 PTC2.1@82.25,83.784
NetPTC3_1: PTC3.1 R112.1 | length 2.4
  Bottom Layer w0.5: R112.1@77.925,102 PTC3.1@80.284,102
NetPTC4_1: PTC4.1 R113.1 | length 2.4
  Bottom Layer w0.5: R113.1@77.925,98 PTC4.1@80.284,98
NetQ1_3: Q1.3 R69.1 | length 3.6
  Bottom Layer w0.15: R69.1@3.15,20.5 3.525,20.875 3.525,20.983 3.9,21.358 3.9,22.4 3.25,23.05 Q1.3@3.25,23.475
NetQ1_6: Q1.6 R68.1 | length 2.3
  Bottom Layer w0.15: R68.1@1.35,20.5 1.35,21.733 1.742,22.125 Q1.6@2.25,22.125
NetQ2_3: Q2.3 R73.1 | length 4.1
  Bottom Layer w0.15: Q2.3@5.45,23.475 5.45,22.888 5.594,22.744 6.199,22.744 6.6,22.342 6.6,21.85 6.225,21.475 6.225,20.875 R73.1@5.85,20.5
NetQ2_6: Q2.6 R72.1 | length 1.8
  Bottom Layer w0.15: R72.1@4.05,20.5 4.159,20.609 4.159,20.937 4.292,21.07 4.292,21.535 4.45,21.692 Q2.6@4.45,22.125
NetQ3_3: Q3.3 R77.1 | length 4
  Bottom Layer w0.15: Q3.3@13.114,23.49 13.114,23.415 13.714,22.815 13.964,22.815 14.325,22.454 14.325,21.876 13.514,21.065 R77.1@13.514,20.515
NetQ3_6: Q3.6 R76.1 | length 1.8
  Bottom Layer w0.15: R76.1@11.714,20.515 12.089,20.89 12.089,21.582 12.114,21.607 Q3.6@12.114,22.14
NetQ4_3: Q4.3 R83.1 | length 4
  Bottom Layer w0.15: Q4.3@15.714,23.49 16.141,23.49 16.864,22.766 16.864,21.165 R83.1@16.214,20.515
NetQ4_6: Q4.6 R80.1 | length 1.7
  Bottom Layer w0.15: R80.1@14.414,20.515 14.414,21.32 14.714,21.62 Q4.6@14.714,22.14
NetQ9_3: Q9.3 Q9.6 R158.2 R160.1 | length 8.6
  Bottom Layer w0.15: R160.1@108.71,54.3 109.908,54.3 111.3,55.692 R158.2@111.3,57.2 111.6,57.2 112.025,57.625 112.025,57.688 112.4,58.063 Q9.6@112.4,58.5 111.813,58.5 111.725,58.588 111.725,59.044 111.344,59.425 111.125,59.425 Q9.3@111.05,59.5
NetQ10_3: Q10.3 Q10.6 R159.2 R162.1 | length 8.2
  Bottom Layer w0.15: R162.1@108.7,77.65 109.997,77.65 111.3,78.953 R159.2@111.3,80.253 111.575,80.253 112,80.678 112,81.478 Q10.6@112.075,81.553 111.547,81.553 111.297,81.803 111.297,82.232 111.047,82.482 110.796,82.482 Q10.3@110.725,82.553
NetQ13_3: Q13.3 R47.1 | length 20.9
  Top Layer w0.15: R47.1@16.7,24.025 20.075,24.025 21.25,22.85 21.25,14.45 19.35,12.55 18.35,12.55 16.75,10.95 Q13.3@16.75,9.4
NetQ14_3: Q14.3 R123.1 | length 3.1
  Bottom Layer w0.15: Q14.3@57,17.475 57.375,17.475 57.6,17.25 57.6,16.3 57.85,16.05 R123.1@57.85,14.95
NetQ14_6: Q14.6 R124.1 | length 1.5
  Bottom Layer w0.15: Q14.6@56,16.125 56.075,16.05 56.075,15.725 R124.1@56.85,14.95
NetR8_2: R8.2 U3.17 | length 71.6
  L1-Signal w0.15: v1(54.6,27.1) 57.623,27.1 57.999,27.476 57.999,28.649 64.6,35.25 64.6,37.6 70.75,43.75 70.75,51.774 71.9,52.924 71.9,60.85 76.25,65.2 83.45,65.2 84.638,66.388 84.638,68.612 80.975,72.275 v1(77.15,72.275)
  Bottom Layer w0.15: R8.2@54.15,25.5 54.15,26.65 v1(54.6,27.1) ; U3.17@77.15,71.45 v1(77.15,72.275)
NetR12_2: R12.2 U8.21 | length 2.1
  Bottom Layer w0.15: U8.21@34.459,27.747 35.647,27.747 35.95,28.05 R12.2@36.45,28.05
NetR13_2: R13.2 U8.22 | length 2.1
  Bottom Layer w0.15: U8.22@34.459,27.347 35.753,27.347 35.95,27.15 R13.2@36.45,27.15
NetR17_2: R17.2 U8.24 | length 2.5
  Bottom Layer w0.15: U8.24@34.459,26.547 35.128,26.547 36.1,25.575 36.225,25.575 R17.2@36.45,25.35
NetR18_2: R18.2 U8.23 | length 2.3
  Bottom Layer w0.15: U8.23@34.459,26.947 35.403,26.947 36.013,26.337 36.363,26.337 R18.2@36.45,26.25
NetR19_1: R19.1 U8.26 | length 4.7
  Bottom Layer w0.15: U8.26@34.459,25.747 35.353,25.747 35.85,25.25 35.85,25.032 36.057,24.825 36.759,24.825 37.484,24.1 R19.1@38.35,24.1
NetR19_2: R19.2 R20.1 | length 1.7
  Bottom Layer w0.15: R20.1@38.341,20.75 38.341,22.391 R19.2@38.35,22.4
NetR21_1: R21.1 U8.2 | length 3.8
  Top Layer w0.15: R21.1@26.3,31.35 26.475,31.175 v1(26.475,30.6)
  Bottom Layer w0.15: v1(26.475,30.6) 26.475,30.722 26.6,30.847 26.6,30.85 26.875,31.125 27.625,31.125 27.825,30.925 27.825,30.413 27.786,30.374 27.786,30.344 27.738,30.296 27.738,29.722 U8.2@27.711,29.695
NetR24_1: R24.1 R25.2 U9.7 | length 5.7
  Top Layer w0.15: R24.1@32.443,33.65 32.743,33.65 ; U9.7@32.735,37.05 32.735,36.092 33.227,35.6 33.85,35.6 34.05,35.4 34.05,34.296 R25.2@33.404,33.65 32.9,33.65 ; 32.743,33.65 32.9,33.65 ; 32.743,33.65 32.9,33.65
NetR25_1: R25.1 R26.2 | length 1
  Top Layer w0.15: R25.1@34.404,33.65 R26.2@35.404,33.65
NetR28_1: R28.1 R29.1 U11.3 | length 4.1
  Top Layer w0.15: R29.1@58.5,42.5 58.925,42.075 58.925,41.915 R28.1@59.765,41.075 U11.3@59.765,38.9
NetR30_1: R30.1 R31.1 U12.3 | length 3.5
  Top Layer w0.25: U12.3@82.935,38.6 83,38.535 R30.1@83,36.55 84.378,36.55 R31.1@84.4,36.528
NetR32_2: R32.2 U11.4 | length 2.1
  Top Layer w0.15: R32.2@58.175,40.9 58.495,40.58 U11.4@58.495,38.9
NetR33_2: R33.2 R34.2 U12.4 | length 2.5
  Top Layer w0.25: U12.4@84.205,38.6 85.778,38.6 R34.2@85.8,38.578 R33.2@85.8,37.678
NetR36_1: R36.1 R37.2 | length 1.1
  Top Layer w0.25: R37.2@87,65.95 87.075,65.875 87.975,65.875 R36.1@88.05,65.8
NetR41_2: R41.2 R43.1 | length 2.1
  Top Layer w0.25: R43.1@85.275,19.35 85.287,19.338 85.287,17.238 R41.2@85.3,17.225
NetR45_1: R45.1 R46.2 | length 1.1
  Top Layer w0.15: R46.2@85.6,41.478 R45.1@85.6,42.578
NetR59_1: R59.1 R60.2 U13.3 X21.1 | length 4.5
  Bottom Layer w0.15: X21.1@16.6,53 R60.2@16.6,51.4 R59.1@18.2,51.4 ; U13.3@18.25,50 R59.1@18.25,51.35
NetR62_2: R62.2 U14.5 | length 1.4
  Bottom Layer w0.15: R62.2@3.45,29.5 3.5,29.55 U14.5@4.85,29.55
NetR64_2: R64.2 U13.4 | length 2.8
  Bottom Layer w0.15: U13.4@18.65,50 18.65,50.35 18.85,50.55 20.2,50.55 R64.2@20.75,50
NetR86_1: R86.1 U18.5 | length 3.7
  Top Layer w0.25: v1(104.084,7.809) 104.999,7.809 R86.1@105,7.81
  Bottom Layer w0.15: v1@104.084,7.78 105.435,7.78 U18.5@105.45,7.795
  Bottom Layer w0.25: v1@104.085,7.81 U18.5@105.465,7.81
NetR87_1: R87.1 U19.5 | length 2.5
  Bottom Layer w0.15: R87.1@92,20.4 v1(92.75,20.4) 92.872,20.4 93.037,20.235 U19.5@94.35,20.235 U19.5@94.315,20.2
NetR88_2: R88.2 U18.4 | length 2.2
  Bottom Layer w0.25: R88.2@103.3,6.58 103.328,6.552 104.041,6.552 v1(104.069,6.524) ; v1(104.069,6.524) U18.4@105.45,6.525
NetR89_2: R89.2 U19.4 | length 2.4
  Bottom Layer w0.15: R89.2@92,19.1 v1@92.732,19.1 ; v1(92.754,19.122) 92.876,19.122 93.034,18.965 U19.4@94.35,18.965 U19.4@94.315,19
NetR119_1: R119.1 U26.14 | length 3.6
  Bottom Layer w0.15: R119.1@42.175,20.225 42.262,20.312 42.262,21.212 42.875,21.825 U26.14@44.6,21.825
NetR125_1: R125.1 U29.2 U29.4 | length 7
  Top Layer w0.15: v1(57.15,28.15) 59.265,28.15 v1(60.515,26.9)
  Bottom Layer w0.15: U29.2@57.13,26.9 57.15,26.92 v1(57.15,28.15) v1@57.15,28.24 ; U29.4@59.67,26.9 v1(60.515,26.9) R125.1@61.45,26.9
NetR126_1: R126.1 U30.2 U30.4 | length 6.4
  L1-Signal w0.15: v1(65.025,27.978) 65.147,27.978 65.319,28.15 v1(67.035,28.15)
  Bottom Layer w0.15: U30.2@64.5,26.9 64.637,27.037 64.637,27.389 64.939,27.69 64.939,27.892 v1(65.025,27.978) ; v1(67.035,28.15) 67.035,26.905 U30.4@67.04,26.9
  Bottom Layer w0.25: U30.4@67.04,26.9 67.09,26.95 R126.1@68.825,26.95
NetR127_1: R127.1 R128.1 U29.7 | length 3.6
  Bottom Layer w0.25: U29.7@57.13,21.9 57.1,21.87 R128.1@57.1,19.8 57.211,19.689 57.211,19.071 57.333,18.949 57.333,18.582 R127.1@57.465,18.45
NetR129_1: R129.1 R130.1 U30.7 | length 5.6
  Bottom Layer w0.15: R129.1@61.4,19.345 R130.1@61.4,20.65 64.412,20.65 64.5,20.738 U30.7@64.5,21.9
NetR134_2: R134.2 U31.7 U31.8 | length 5.4
  Top Layer w0.15: U31.8@52.58,100.575 54.075,100.575 ; U31.7@52.58,101.225 53.762,101.225 54.075,100.912 54.075,100.575 ; R134.2@55,99 55,99.65 54.075,100.575
NetR149_1: R149.1 R150.2 U32.7 | length 2.8
  Top Layer w0.25: R150.2@35.55,54.05 R149.1@36.55,54.05 36.53,54.03 U32.7@36.53,52.3
NetR154_1: R154.1 R155.1 U35.3 | length 3.5
  Bottom Layer w0.15: R155.1@14,26.25 14,27.704 U35.3@14.026,27.731 15.981,27.731 R154.1@16,27.75
NetR156_1: R156.1 U35.5 | length 2
  Bottom Layer w0.15: R156.1@9.85,27.9 9.85,27.95 10.275,28.375 10.325,28.375 10.631,28.681 U35.5@11.516,28.681
NetR158_1: R158.1 R161.1 U37.5 | length 10.3
  Bottom Layer w0.15: R161.1@108.717,53.4 109.45,53.4 110.05,54 R158.1@111.3,54 111.3,54.9 112.948,56.548 115.584,56.548 115.975,56.157 U37.5@115.975,55.073
NetR159_1: R159.1 R163.1 U38.5 | length 9.1
  Bottom Layer w0.15: R159.1@111.3,77.053 111.3,78.022 112.253,78.975 115.387,78.975 115.475,78.887 U38.5@115.475,78.126
  Bottom Layer w0.25: R163.1@108.7,76.75 109.3,76.75 109.603,77.053 R159.1@111.3,77.053
NetR176_2: R176.2 U44.4 | length 6.5
  Bottom Layer w0.15: R176.2@91.55,70.6 92.2,69.95 94.55,69.95 94.8,69.7 94.8,68.2 94.628,68.028 U44.4@93.45,68.028
NetR177_1: R177.1 U44.5 | length 1.7
  Bottom Layer w0.25: R177.1@91.75,69.318 93.43,69.318 U44.5@93.45,69.298
NetR178_2: R178.2 U46.4 | length 2
  Bottom Layer w0.25: R178.2@91.6,91.653 92.479,91.653 92.625,91.507 92.625,91.493 92.8,91.318 U46.4@93.45,91.318
NetR179_1: R179.1 U46.5 | length 1.9
  Bottom Layer w0.25: R179.1@91.6,92.553 93.415,92.553 U46.5@93.45,92.588
NetR182_2: R182.2 U47.7 U47.8 | length 7.1
  Bottom Layer w0.15: R182.2@86.15,48.545 86.429,48.824 87.275,48.824 87.436,48.985 87.867,48.985 88.932,50.05 ; U47.7@89,51.59 89,50.118 88.932,50.05 ; U47.8@89.65,51.59 89.65,50.35 89.35,50.05 89,50.05 88.932,50.05
NetR186_1: R186.1 R241.2 U50.3 | length 9.4
  Top Layer w0.25: v1(93.384,26.662) 92.95,27.096 R186.1@92.95,28.15 93.8,28.15 93.935,28.285 96.159,28.285 U50.3@96.191,28.252
  Bottom Layer w0.25: v1(93.384,26.662) 94.795,26.662 95.433,27.3 R241.2@97.5,27.3
NetR187_1: R187.1 U49.5 | length 1.7
  Bottom Layer w0.25: R187.1@92.522,32.723 92.557,32.758 U49.5@94.172,32.758
NetR188_2: R188.2 U49.4 | length 1.7
  Bottom Layer w0.25: R188.2@92.522,31.523 92.557,31.488 U49.4@94.172,31.488
NetR189_1: R189.1 U50.7 U52.4 | length 17.7
  Top Layer w0.15: U50.7@101.66,29.53 v1(105.242,29.53) 105.862,30.15 111.8,30.15 112.955,28.995 U52.4@112.955,27.869
  Bottom Layer w0.15: R189.1@100.7,29.5 100.73,29.53 v1(105.242,29.53)
NetR191_1: R191.1 U53.5 | length 1.9
  Bottom Layer w0.25: R191.1@92.5,44.607 92.504,44.603 U53.5@94.35,44.603
NetR192_2: R192.2 U53.4 | length 1.9
  Bottom Layer w0.25: R192.2@92.5,43.307 92.526,43.333 U53.4@94.35,43.333
NetR193_1: R193.1 U62.1 | length 1.4
  Top Layer w0.15: R193.1@90.255,89.348 U62.1@90.255,90.748
NetR193_2: R193.2 U60.2 | length 1.2
  Top Layer w0.15: U60.2@90.255,87.198 R193.2@90.255,88.348
NetR194_1: R194.1 U63.1 | length 1.4
  Top Layer w0.15: R194.1@83.325,89.3 U63.1@83.325,90.7
NetR194_2: R194.2 U61.2 | length 1.2
  Top Layer w0.15: U61.2@83.325,87.15 R194.2@83.325,88.3
NetR195_1: R195.1 U60.4 | length 1.6
  Top Layer w0.15: R195.1@89.205,83.848 89.205,84.673 89.605,85.073 U60.4@89.605,85.298
NetR196_1: R196.1 U61.4 | length 1.6
  Top Layer w0.15: R196.1@82.275,83.8 82.275,84.625 82.675,85.025 U61.4@82.675,85.25
NetR203_1: R203.1 R204.2 U65.7 | length 2.8
  Bottom Layer w0.15: U65.7@20.725,96.915 20.76,96.95 R203.1@22.625,96.95 R204.2@22.625,96.05
NetR204_1: R204.1 R205.2 | length 0.9
  Bottom Layer w0.15: R205.2@23.625,95.15 R204.1@23.625,96.05
NetR206_2: R206.2 U64.5 | length 1.3
  Bottom Layer w0.15: U64.5@6.705,96.028 R206.2@8.031,96.028
NetR211_1: R211.1 R212.2 U8.17 | length 4
  Bottom Layer w0.15: U8.17@33.711,29.695 33.738,29.722 33.738,30.388 34.2,30.85 R212.2@36.05,30.85 ; R211.1@36.05,29.95 R212.2@36.05,30.7
NetR213_1: R213.1 R216.2 | length 1.6
  Bottom Layer w0.25: R216.2@17.831,15.35 R213.1@19.39,15.35
NetR213_2: R213.2 U68.5 | length 1.8
  Bottom Layer w0.15: R213.2@19.39,17.05 19.611,17.271 U68.5@19.611,18.745
NetR215_2: R215.2 U16.1 | length 2.5
  Top Layer w0.15: U16.1@43.65,40.825 44.287,40.825 44.562,40.55 v1(44.6,40.55)
  Bottom Layer w0.15: R215.2@43.35,41 43.8,41 44.204,40.596 44.554,40.596 v1(44.6,40.55)
NetR218_2: R218.2 S2.1 U4.6 | length 9.9
  Bottom Layer w0.15: R218.2@15.55,9.825 16.55,9.825 18.35,8.025 18.35,5.525 17.95,5.125 U4.6@17.005,5.125 17.005,3.92 17.825,3.1 S2.1@17.85,3.1
NetR219_2: R219.2 S1.1 U4.1 | length 9.6
  Bottom Layer w0.15: S1.1@12.775,3.125 13.65,3.125 14.495,3.97 U4.1@14.495,5.125 13.4,5.125 12.975,5.55 12.975,7.25 14.05,8.325 R219.2@14.05,9.825
NetR222_2: R222.2 U16.10 | length 1.5
  Top Layer w0.15: U16.10@43.65,44.425 45.075,44.425 R222.2@45.1,44.4
NetR234_2: R234.2 U20.7 U22.1 | length 6.3
  Top Layer w0.15: U20.7@112.28,7.795 113.455,7.795 113.653,7.597 113.653,7.148 v1(113.64,7.135) ; v1@113.7,7.15 113.7,7.103 114.022,6.781 114.022,5.542 114.249,5.315 U22.1@114.7,5.315
  Bottom Layer w0.25: R234.2@111.816,7.176 111.856,7.135 v1(113.64,7.135)
NetR235_2: R235.2 U20.6 U22.4 | length 9.8
  Top Layer w0.15: U20.6@112.08,6.58 112.338,6.322 113.158,6.322 113.522,5.958 113.522,4.922 113.275,4.675 113.275,3.975 v1(113.2,3.9) 113.2,1.803 113.498,1.505 U22.4@114.7,1.505
  Bottom Layer w0.25: R235.2@111.6,5.015 111.6,4.715 112.415,3.9 v1(113.2,3.9)
NetR238_2: R238.2 U21.7 U23.1 | length 5.4
  Top Layer w0.15: U21.7@101.181,20.235 101.816,20.235 102.058,20.478 102.058,20.574 102.148,20.664 102.414,20.664 v1(102.5,20.75) 102.586,20.664 102.813,20.664 102.923,20.554 102.923,20.442 103.165,20.2 U23.1@103.8,20.2
  Bottom Layer w0.15: R238.2@100.7,21.8 101.45,21.8 v1(102.5,20.75)
NetR239_2: R239.2 U21.6 U23.4 | length 6.7
  Top Layer w0.15: U21.6@101.181,18.965 102.285,18.965 102.49,18.76 v1(102.49,17.014) 102.871,16.632 103.59,16.632 103.816,16.406 U23.4@103.8,16.39
  Bottom Layer w0.15: R239.2@100.7,17.4 102.103,17.4 v1(102.49,17.014)
NetR241_1: R241.1 U50.6 U52.1 | length 13.2
  Top Layer w0.2: U50.6@101.652,28.252 104.757,28.252 104.767,28.242 104.958,28.242 v1(105.5,27.7) 107.7,27.7 107.869,27.869 U52.1@109.145,27.869
  Bottom Layer w0.2: R241.1@100.7,27.3 101.652,27.3 102.605,28.252 104.757,28.252 104.767,28.242 104.958,28.242 v1(105.5,27.7)
NetR242_1: R242.1 U51.7 U52.3 | length 20.9
  Top Layer w0.2: U51.7@101.652,35.298 101.686,35.264 102.788,35.264 103.402,34.65 v1(105.804,34.65)
  Top Layer w0.25: U52.3@111.685,27.869 v1@111.685,29.309
  Bottom Layer w0.15: v1(105.804,34.65) 108.979,34.65 111.693,31.936 v1(111.693,29.317)
  Bottom Layer w0.2: R242.1@100.7,33.9 101.6,33.9 102.35,34.65 v1(105.804,34.65)
NetR245_1: R245.1 U55.7 U56.10 | length 14.4
  Top Layer w0.15: U55.7@101.831,47.464 103.036,47.464 103.807,46.693 106.443,46.693 106.773,47.023 107.173,47.023 v1(107.85,47.7)
  Bottom Layer w0.15: R245.1@100.7,48.118 101.462,48.118 101.85,47.73 105.28,47.73 105.625,48.075 107.475,48.075 v1(107.85,47.7)
NetR246_1: R246.1 U55.6 U56.9 | length 16.9
  Top Layer w0.15: U55.6@101.831,46.194 101.766,46.259 100.741,46.259 100.55,46.45 100.55,47.9 100.768,48.118 103.082,48.118 103.857,47.343 U56.9@105.225,47.343 105.256,47.374 106.237,47.374 106.325,47.462 106.325,48.675 v1(105.45,49.55)
  Bottom Layer w0.25: R246.1@100.7,50.318 101.682,50.318 102.8,49.2 104.2,49.2 104.55,49.55 v1(105.45,49.55)
NetR247_1: R247.1 U54.7 U56.11 | length 15.7
  Top Layer w0.15: U54.7@101.808,41.664 103.114,41.664 103.6,42.15 103.6,45.6 104.043,46.043 U56.11@105.225,46.043 106.643,46.043 v1(107,46.4)
  Bottom Layer w0.25: R247.1@100.7,45.918 101.918,45.918 102.448,46.448 104.914,46.448 104.962,46.4 v1(107,46.4)
NetR248_1: R248.1 U54.6 U56.12 | length 17.8
  Top Layer w0.15: U54.6@101.808,40.394 103.194,40.394 103.95,41.15 103.95,45.15 104.193,45.393 U56.12@105.225,45.393 106.307,45.393 106.9,44.8 v1(107.35,44.8)
  Bottom Layer w0.15: R248.1@100.7,43.718 100.7,44.018 101.125,44.443 101.213,44.443 101.898,45.128 105.398,45.128 105.721,44.805 105.721,44.801 105.809,44.713 107.037,44.713 107.038,44.714 107.264,44.714 v1(107.35,44.8)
